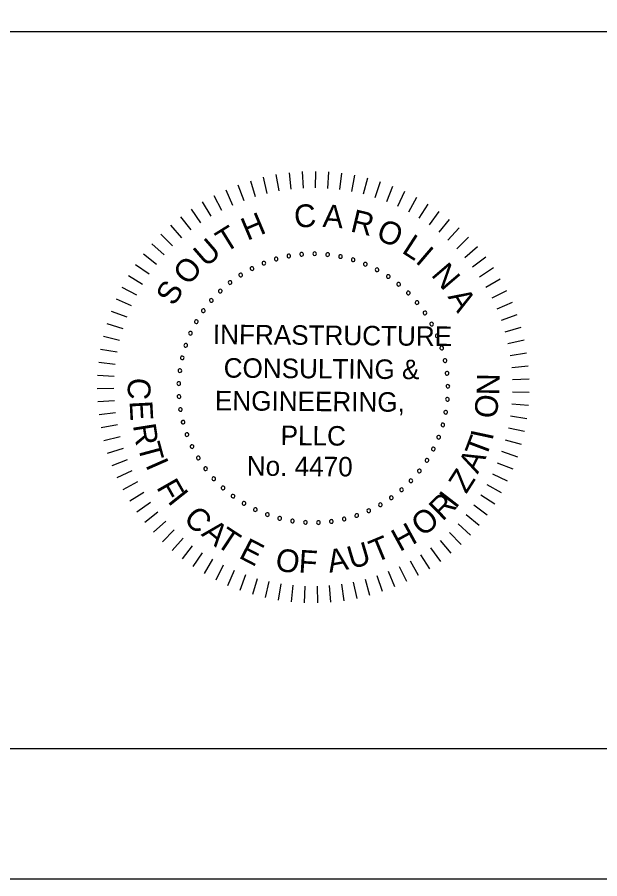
# Model space of a CAD drawing. Extents: x -448.1 to -400, y -140.7 to -111.4.
# Drawn here: x -414.536 to -411.56, y -140.698 to -136.292 of the extents above; entities that cross this region are included whole.
import ezdxf

# ---------------------------------------------------------------- set-up
doc = ezdxf.new("R2010")
doc.units = 0
for name, color, linetype in [('BR_BORDER LINES', 7, 'Continuous'), ('BR_TEXT', 7, 'Continuous'), ('Level 31', 7, 'Continuous')]:
    doc.layers.add(name, color=color, linetype=linetype)

msp = doc.modelspace()

# ---------------------------------------------------------------- linework, layer by layer
at = {"layer": 'BR_BORDER LINES'}
for p, q in [((-417.955, -136.3641), (-410.8014, -136.3641)), ((-445.689, -140.0309), (-400.801, -140.0309))]:
    msp.add_line(p, q, dxfattribs=at)
at = {"layer": 'BR_TEXT'}
for p, q in [((-413.2797, -137.1099), (-413.2599, -137.1924)), ((-413.2138, -137.0962), (-413.199, -137.1798)), ((-413.1472, -137.0866), (-413.1375, -137.171)), ((-413.0801, -137.0811), (-413.0756, -137.1659)), ((-413.0128, -137.0797), (-413.0135, -137.1646)), ((-412.9455, -137.0824), (-412.9514, -137.1671)), ((-412.8786, -137.0892), (-412.8896, -137.1733)), ((-412.8121, -137.1), (-412.8283, -137.1834)), ((-413.4084, -137.149), (-413.3787, -137.2286)), ((-413.3447, -137.1275), (-413.3199, -137.2087)), ((-412.7465, -137.1149), (-412.7677, -137.1971)), ((-412.6819, -137.1338), (-412.708, -137.2145)), ((-412.6185, -137.1565), (-412.6496, -137.2355)), ((-413.4708, -137.1744), (-413.4363, -137.252)), ((-412.5567, -137.1831), (-412.5925, -137.2601)), ((-413.5902, -137.2364), (-413.5465, -137.3092)), ((-413.5315, -137.2036), (-413.4923, -137.2789)), ((-412.4966, -137.2134), (-412.537, -137.2881)), ((-413.6469, -137.2727), (-413.5988, -137.3427)), ((-412.4384, -137.2473), (-412.4833, -137.3194)), ((-412.3825, -137.2847), (-412.4317, -137.3539)), ((-413.7012, -137.3124), (-413.649, -137.3794)), ((-412.3289, -137.3255), (-412.3822, -137.3915)), ((-413.7531, -137.3554), (-413.6969, -137.419)), ((-412.2779, -137.3694), (-412.3351, -137.4321)), ((-413.8022, -137.4014), (-413.7422, -137.4615)), ((-412.2297, -137.4163), (-412.2906, -137.4754)), ((-413.8484, -137.4504), (-413.7849, -137.5067)), ((-413.8915, -137.502), (-413.8247, -137.5544)), ((-412.1844, -137.4661), (-412.2488, -137.5214)), ((-412.1422, -137.5186), (-412.2099, -137.5698)), ((-413.9315, -137.5562), (-413.8615, -137.6044)), ((-412.1033, -137.5736), (-412.1741, -137.6206)), ((-413.968, -137.6128), (-413.8953, -137.6566)), ((-412.0679, -137.6308), (-412.1413, -137.6734)), ((-414.001, -137.6714), (-413.9258, -137.7107)), ((-412.036, -137.6901), (-412.1119, -137.7281)), ((-414.0304, -137.732), (-413.9529, -137.7666)), ((-412.0078, -137.7512), (-412.0858, -137.7845)), ((-414.056, -137.7942), (-413.9766, -137.8241)), ((-411.9833, -137.8139), (-412.0633, -137.8424)), ((-414.0778, -137.8579), (-413.9967, -137.8828)), ((-411.9627, -137.878), (-412.0443, -137.9015)), ((-414.0957, -137.9228), (-414.0132, -137.9427)), ((-411.9461, -137.9432), (-412.0289, -137.9618)), ((-414.1096, -137.9887), (-414.026, -138.0035)), ((-411.9334, -138.0093), (-412.0173, -138.0228)), ((-414.1194, -138.0553), (-414.0351, -138.065)), ((-411.9249, -138.0761), (-412.0094, -138.0844)), ((-414.1252, -138.1223), (-414.0404, -138.1269)), ((-411.9204, -138.1432), (-412.0052, -138.1464)), ((-414.1269, -138.1896), (-414.042, -138.189)), ((-411.92, -138.2105), (-412.0049, -138.2085)), ((-414.1244, -138.2569), (-414.0397, -138.2511)), ((-411.9237, -138.2777), (-412.0083, -138.2706)), ((-414.1179, -138.3239), (-414.0337, -138.313)), ((-411.9315, -138.3446), (-412.0155, -138.3323)), ((-414.1073, -138.3903), (-414.0239, -138.3743)), ((-411.9434, -138.4109), (-412.0265, -138.3935)), ((-414.0926, -138.456), (-414.0104, -138.435)), ((-411.9593, -138.4763), (-412.0411, -138.4538)), ((-414.074, -138.5207), (-413.9932, -138.4947)), ((-411.9791, -138.5406), (-412.0595, -138.5132)), ((-414.0515, -138.5842), (-413.9724, -138.5532)), ((-414.0251, -138.6461), (-413.9481, -138.6104)), ((-412.0028, -138.6036), (-412.0814, -138.5713)), ((-412.0304, -138.665), (-412.1068, -138.628)), ((-413.995, -138.7063), (-413.9203, -138.666)), ((-412.0616, -138.7246), (-412.1356, -138.6831)), ((-413.9613, -138.7646), (-413.8892, -138.7198)), ((-412.0964, -138.7823), (-412.1677, -138.7363)), ((-413.9242, -138.8207), (-413.8549, -138.7716)), ((-413.8836, -138.8744), (-413.8175, -138.8212)), ((-412.1346, -138.8377), (-412.203, -138.7874)), ((-413.8399, -138.9256), (-413.7771, -138.8684)), ((-412.1762, -138.8906), (-412.2414, -138.8363)), ((-413.7931, -138.974), (-413.734, -138.9131)), ((-412.2209, -138.9409), (-412.2827, -138.8827)), ((-413.7435, -139.0195), (-413.6881, -138.9551)), ((-412.2685, -138.9885), (-412.3267, -138.9266)), ((-413.6911, -139.0618), (-413.6399, -138.9942)), ((-412.3722, -139.0743), (-412.4223, -139.0058)), ((-412.319, -139.033), (-412.3733, -138.9677)), ((-413.6363, -139.1009), (-413.5893, -139.0302)), ((-412.4277, -139.1124), (-412.4736, -139.0409)), ((-413.5793, -139.1366), (-413.5366, -139.0632)), ((-413.5201, -139.1687), (-413.482, -139.0928)), ((-412.4854, -139.1469), (-412.5269, -139.0729)), ((-413.4591, -139.1971), (-413.4257, -139.1191)), ((-412.6067, -139.2052), (-412.6389, -139.1267)), ((-412.5452, -139.1779), (-412.5821, -139.1015)), ((-413.3965, -139.2218), (-413.3679, -139.1419)), ((-413.3325, -139.2427), (-413.3088, -139.1611)), ((-413.2673, -139.2595), (-413.2486, -139.1767)), ((-412.7997, -139.264), (-412.817, -139.1809)), ((-412.7342, -139.2483), (-412.7565, -139.1664)), ((-412.6698, -139.2287), (-412.6971, -139.1483)), ((-413.2012, -139.2724), (-413.1877, -139.1886)), ((-413.1345, -139.2812), (-413.1261, -139.1968)), ((-413.0674, -139.286), (-413.0641, -139.2011)), ((-413.0001, -139.2866), (-413.002, -139.2017)), ((-412.9328, -139.2831), (-412.9399, -139.1985)), ((-412.866, -139.2756), (-412.8782, -139.1916))]:
    msp.add_line(p, q, dxfattribs=at)
for centre, start, end in [((-413.1483, -137.5127), 10.6038, 190.6038), ((-413.0824, -137.5038), 5.0653, 185.0653), ((-413.0824, -137.5038), 185.0653, 5.0653), ((-413.016, -137.5012), 359.5268, 179.5268), ((-413.016, -137.5012), 179.5268, 359.5268), ((-412.9497, -137.5051), 173.9884, 353.9884), ((-412.9497, -137.5051), 353.9884, 173.9884), ((-412.8841, -137.5154), 348.4499, 168.4499), ((-413.2758, -137.5493), 21.6807, 201.6807), ((-413.2758, -137.5493), 201.6807, 21.6807), ((-413.2129, -137.5279), 16.1422, 196.1422), ((-413.2129, -137.5279), 196.1422, 16.1422), ((-413.1483, -137.5127), 190.6038, 10.6038), ((-412.8841, -137.5154), 168.4499, 348.4499), ((-412.8197, -137.5319), 162.9114, 342.9114), ((-412.8197, -137.5319), 342.9114, 162.9114), ((-412.7573, -137.5546), 157.373, 337.373), ((-412.7573, -137.5546), 337.373, 157.373), ((-413.3364, -137.5767), 27.2191, 207.2191), ((-413.3364, -137.5767), 207.2191, 27.2191), ((-412.6973, -137.5833), 151.8345, 331.8345), ((-412.6973, -137.5833), 331.8345, 151.8345), ((-413.4481, -137.6483), 38.2961, 218.2961), ((-413.394, -137.6098), 32.7576, 212.7576), ((-413.394, -137.6098), 212.7576, 32.7576), ((-412.6404, -137.6175), 146.2961, 326.2961), ((-412.6404, -137.6175), 326.2961, 146.2961), ((-413.4983, -137.6919), 43.8345, 223.8345), ((-413.4481, -137.6483), 218.2961, 38.2961), ((-412.587, -137.6571), 140.7576, 320.7576), ((-412.587, -137.6571), 320.7576, 140.7576), ((-413.4983, -137.6919), 223.8345, 43.8345), ((-412.5378, -137.7017), 135.2191, 315.2191), ((-412.5378, -137.7017), 315.2191, 135.2191), ((-413.5441, -137.74), 49.373, 229.373), ((-413.5441, -137.74), 229.373, 49.373), ((-412.493, -137.7508), 129.6807, 309.6807), ((-412.493, -137.7508), 309.6807, 129.6807), ((-413.5849, -137.7924), 54.9114, 234.9114), ((-413.5849, -137.7924), 234.9114, 54.9114), ((-412.4532, -137.804), 124.1422, 304.1422), ((-412.4532, -137.804), 304.1422, 124.1422), ((-413.6206, -137.8485), 60.4499, 240.4499), ((-413.6206, -137.8485), 240.4499, 60.4499), ((-412.4187, -137.8608), 118.6038, 298.6038), ((-412.4187, -137.8608), 298.6038, 118.6038), ((-413.6506, -137.9077), 65.9884, 245.9884), ((-413.6506, -137.9077), 245.9884, 65.9884), ((-412.3899, -137.9207), 113.0653, 293.0653), ((-412.3899, -137.9207), 293.0653, 113.0653), ((-413.6748, -137.9696), 71.5268, 251.5268), ((-413.6748, -137.9696), 251.5268, 71.5268), ((-412.367, -137.983), 107.5268, 287.5268), ((-412.367, -137.983), 287.5268, 107.5268), ((-413.6929, -138.0335), 77.0653, 257.0653), ((-413.6929, -138.0335), 257.0653, 77.0653), ((-412.3502, -138.0473), 101.9884, 281.9884), ((-412.3502, -138.0473), 281.9884, 101.9884), ((-413.7048, -138.0989), 82.6038, 262.6038), ((-413.7048, -138.0989), 262.6038, 82.6038), ((-412.3397, -138.1129), 96.4499, 276.4499), ((-412.3397, -138.1129), 276.4499, 96.4499), ((-413.7103, -138.1651), 88.1422, 268.1422), ((-413.7103, -138.1651), 268.1422, 88.1422), ((-412.3355, -138.1792), 90.9114, 270.9114), ((-412.3355, -138.1792), 270.9114, 90.9114), ((-413.7094, -138.2316), 93.6807, 273.6807), ((-413.7094, -138.2316), 273.6807, 93.6807), ((-412.3378, -138.2456), 85.373, 265.373), ((-412.3378, -138.2456), 265.373, 85.373), ((-413.702, -138.2976), 99.2191, 279.2191), ((-413.702, -138.2976), 279.2191, 99.2191), ((-412.3465, -138.3115), 79.8345, 259.8345), ((-412.3465, -138.3115), 259.8345, 79.8345), ((-413.6884, -138.3626), 104.7576, 284.7576), ((-413.6884, -138.3626), 284.7576, 104.7576), ((-412.3615, -138.3762), 74.2961, 254.2961), ((-412.3615, -138.3762), 254.2961, 74.2961), ((-413.6685, -138.426), 110.2961, 290.2961), ((-413.6685, -138.426), 290.2961, 110.2961), ((-412.3827, -138.4392), 68.7576, 248.7576), ((-412.3827, -138.4392), 248.7576, 68.7576), ((-413.6426, -138.4872), 295.8345, 115.8345), ((-413.6426, -138.4872), 115.8345, 295.8345), ((-412.4099, -138.4998), 63.2191, 243.2191), ((-412.4099, -138.4998), 243.2191, 63.2191), ((-413.6109, -138.5456), 121.373, 301.373), ((-413.6109, -138.5456), 301.373, 121.373), ((-412.4427, -138.5576), 57.6807, 237.6807), ((-412.4427, -138.5576), 237.6807, 57.6807), ((-413.5737, -138.6007), 126.9114, 306.9114), ((-413.5737, -138.6007), 306.9114, 126.9114), ((-412.481, -138.6119), 52.1422, 232.1422), ((-412.481, -138.6119), 232.1422, 52.1422), ((-413.5314, -138.6519), 132.4499, 312.4499), ((-413.5314, -138.6519), 312.4499, 132.4499), ((-412.5244, -138.6622), 46.6038, 226.6038), ((-413.4843, -138.6988), 137.9884, 317.9884), ((-413.4843, -138.6988), 317.9884, 137.9884), ((-412.5244, -138.6622), 226.6038, 46.6038), ((-413.4329, -138.7409), 143.5268, 323.5268), ((-413.4329, -138.7409), 323.5268, 143.5268), ((-412.6246, -138.7492), 35.5268, 215.5268), ((-412.5724, -138.7081), 41.0653, 221.0653), ((-412.5724, -138.7081), 221.0653, 41.0653), ((-413.3777, -138.7779), 149.0653, 329.0653), ((-413.3777, -138.7779), 329.0653, 149.0653), ((-412.6806, -138.785), 29.9884, 209.9884), ((-412.6806, -138.785), 209.9884, 29.9884), ((-412.6246, -138.7492), 215.5268, 35.5268), ((-413.3192, -138.8094), 154.6038, 334.6038), ((-413.3192, -138.8094), 334.6038, 154.6038), ((-413.2579, -138.835), 340.1422, 160.1422), ((-412.8015, -138.8397), 18.9114, 198.9114), ((-412.7397, -138.8153), 24.4499, 204.4499), ((-412.7397, -138.8153), 204.4499, 24.4499), ((-413.2579, -138.835), 160.1422, 340.1422), ((-413.1945, -138.8547), 165.6807, 345.6807), ((-413.1945, -138.8547), 345.6807, 165.6807), ((-413.1294, -138.8681), 171.2191, 351.2191), ((-413.1294, -138.8681), 351.2191, 171.2191), ((-413.0633, -138.8752), 356.7576, 176.7576), ((-413.0633, -138.8752), 176.7576, 356.7576), ((-412.9969, -138.8759), 2.2961, 182.2961), ((-412.9307, -138.8702), 7.8345, 187.8345), ((-412.9307, -138.8702), 187.8345, 7.8345), ((-412.8654, -138.8581), 13.373, 193.373), ((-412.8654, -138.8581), 193.373, 13.373), ((-412.8015, -138.8397), 198.9114, 18.9114), ((-412.9969, -138.8759), 182.2961, 2.2961)]:
    msp.add_arc(centre, 0.00935, start, end, dxfattribs=at)
at = {"layer": 'Level 31'}
msp.add_lwpolyline([(-448.1334, -140.6975), (-400.1335, -140.6975), (-400.1335, -111.3642), (-448.1334, -111.3642)], close=True, dxfattribs=at)

# ---------------------------------------------------------------- texts
at = {"layer": 'BR_TEXT'}
for s, height, rotation, p in [('C', 0.1163, 4.7281, (-413.1167, -137.3698)), ('A', 0.1163, 355.6981, (-412.9774, -137.3632)), ('R', 0.1163, 346.6681, (-412.8384, -137.3859)), ('H', 0.1163, 22.7882, (-413.3605, -137.4357)), ('O', 0.1163, 337.638, (-412.7081, -137.4256)), ('T', 0.1163, 31.8182, (-413.4736, -137.4992)), ('U', 0.1163, 40.8482, (-413.5714, -137.574)), ('L', 0.1163, 327.108, (-412.5763, -137.4929)), ('I', 0.1163, 319.578, (-412.5062, -137.5433)), ('O', 0.1163, 49.8782, (-413.6607, -137.6687)), ('N', 0.1163, 310.548, (-412.4251, -137.611)), ('S', 0.1163, 58.9083, (-413.7346, -137.773)), ('A', 0.1163, 301.5179, (-412.3384, -137.7209)), ('INFRASTRUCTURE', 0.099695, 359.5268, (-413.5364, -137.963)), ('CONSULTING &', 0.099695, 359.5268, (-413.4814, -138.1345)), ('N', 0.1163, 89.2085, (-412.0726, -138.2259)), ('C', 0.1163, 267.025, (-413.9679, -138.1329)), ('ENGINEERING,', 0.099695, 359.5268, (-413.5261, -138.3017)), ('O', 0.1163, 83.2085, (-412.0874, -138.3478)), ('E', 0.1163, 273.025, (-413.962, -138.255)), ('R', 0.1163, 279.025, (-413.945, -138.378)), ('PLLC', 0.09969, 359.5268, (-413.1905, -138.4798)), ('T', 0.1163, 69.3954, (-412.1424, -138.5502)), ('I', 0.1163, 77.9093, (-412.1081, -138.4602)), ('T', 0.1163, 285.025, (-413.9218, -138.4831)), ('I', 0.1163, 293.7713, (-413.8822, -138.5805)), ('No. 4470', 0.09969, 359.5268, (-413.3633, -138.6357)), ('A', 0.1163, 63.3954, (-412.1834, -138.6306)), ('Z', 0.1163, 57.3954, (-412.2418, -138.7324)), ('F', 0.1163, 299.7713, (-413.8273, -138.6953)), ('I', 0.1163, 308.5268, (-413.7712, -138.7671)), ('R', 0.1163, 44.5268, (-412.3625, -138.8724)), ('I', 0.1163, 52.3339, (-412.2966, -138.8093)), ('C', 0.1163, 314.5268, (-413.692, -138.8606)), ('O', 0.1163, 38.5268, (-412.4646, -138.9523)), ('A', 0.1163, 320.5268, (-413.5998, -138.9387)), ('T', 0.1163, 326.5268, (-413.5272, -138.99)), ('H', 0.1163, 28.5268, (-412.5821, -139.027)), ('E', 0.1163, 332.5268, (-413.4091, -139.0537)), ('T', 0.1163, 22.5268, (-412.7063, -139.0827)), ('U', 0.1163, 16.5268, (-412.8286, -139.1152)), ('O', 0.1163, 350.5268, (-413.2223, -139.1188)), ('F', 0.1163, 356.5268, (-413.1003, -139.131)), ('A', 0.1163, 10.5268, (-412.9405, -139.1332))]:
    msp.add_text(s, height=height, rotation=rotation, dxfattribs=at).set_placement(p)

doc.saveas('drawing.dxf')
